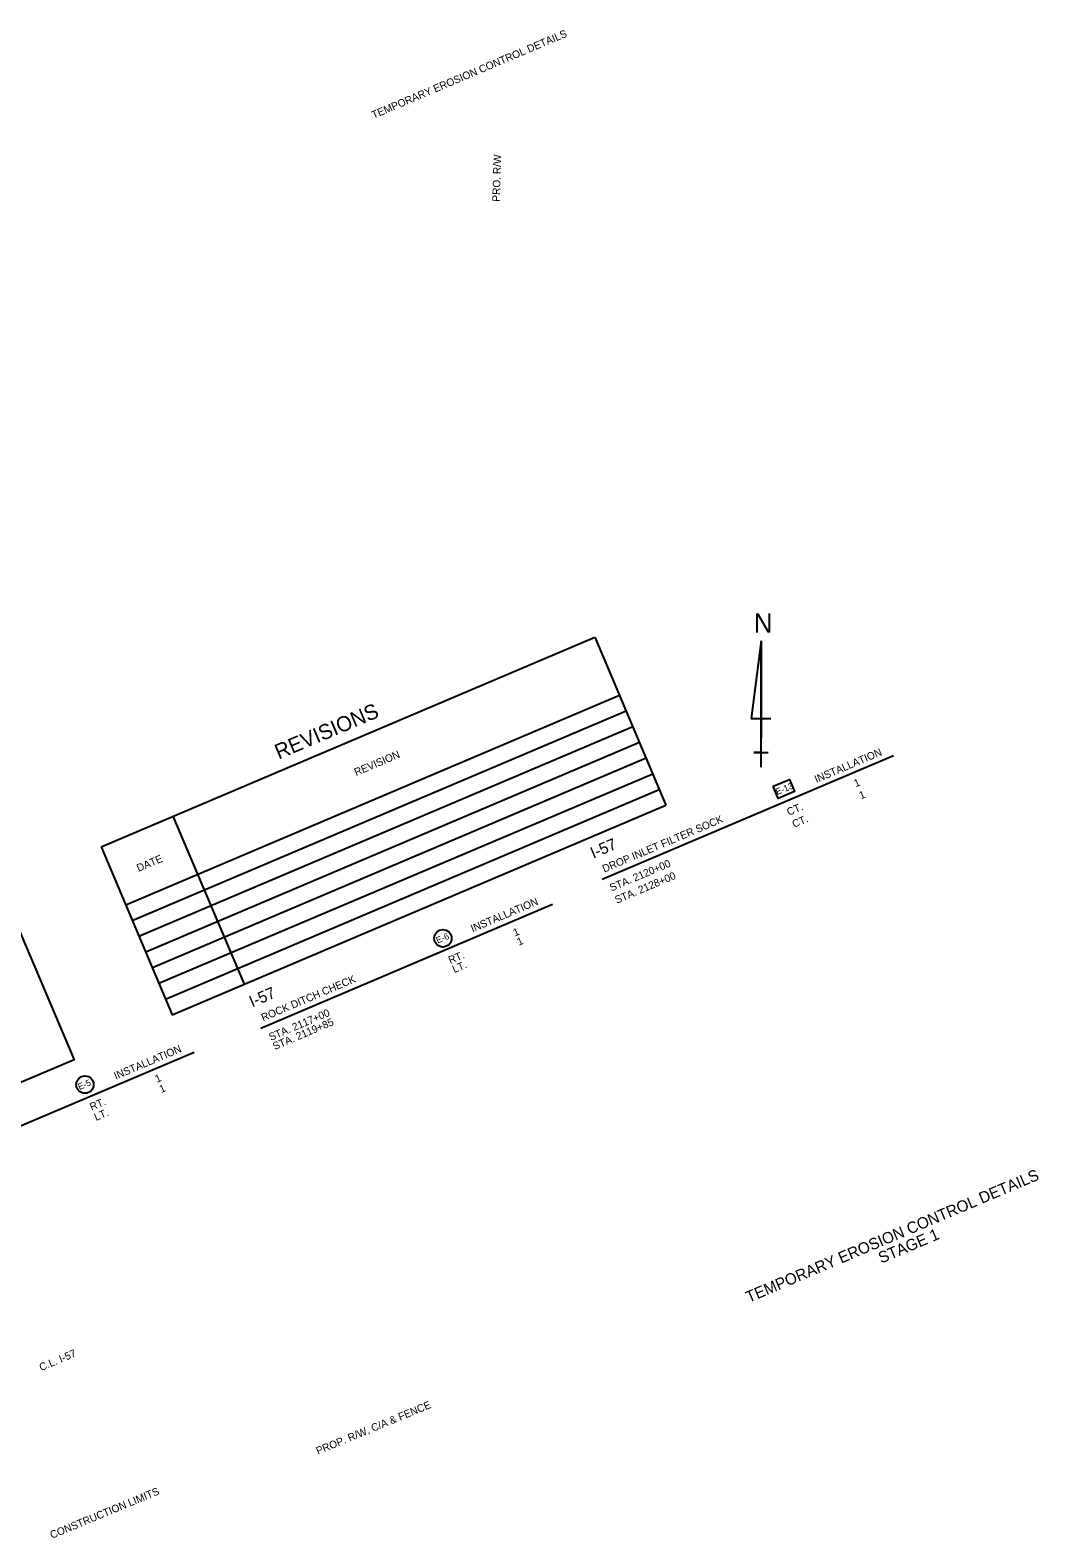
# Model space of a CAD drawing. Extents: x 1716086 to 1717910, y 765525 to 766719.
# Drawn here: x 1717110 to 1717910, y 765525 to 766719 of the extents above; entities that cross this region are included whole.
import ezdxf

# ---------------------------------------------------------------- set-up
doc = ezdxf.new("R2010")
doc.units = 0
for name, color, linetype in [('1', 7, 'Continuous'), ('44', 7, 'Continuous'), ('63', 7, 'Continuous'), ('Default', 7, 'Continuous'), ('G-ANNO-TEXT', 7, 'Continuous'), ('Level 44', 7, 'Continuous'), ('R_Draft', 7, 'Continuous')]:
    doc.layers.add(name, color=color, linetype=linetype)

msp = doc.modelspace()

# ---------------------------------------------------------------- linework, layer by layer
at = {"layer": '1'}
for points in [[(1717699.1, 766120.5), (1717712, 766126), (1717716.1, 766116.3), (1717703.2, 766110.9)], [(1716722.2, 765885.1), (1717087.4, 766040.1), (1717145.2, 765903.9), (1716780, 765749)]]:
    msp.add_lwpolyline(points, close=True, dxfattribs=at)
for centre in [(1717437.4, 766000.1), (1717153.8, 765884.2)]:
    msp.add_circle(centre, 6.88, dxfattribs=at)
at = {"layer": '44'}
for p, q in [((1717563.5, 766046.9), (1717794.5, 766144.9)), ((1717293.2, 765929), (1717524.3, 766027.1)), ((1717010.5, 765812.4), (1717240.2, 765909.9))]:
    msp.add_line(p, q, dxfattribs=at)
at = {"layer": '63'}
for p, q in [((1717689.5, 766235.7), (1717681.8, 766174.2)), ((1717689.5, 766135.7), (1717689.5, 766235.7)), ((1717689.5, 766235.7), (1717689.5, 766158.8)), ((1717681.8, 766174.2), (1717697.2, 766174.2)), ((1717689.5, 766135.7), (1717689.5, 766158.8)), ((1717689.5, 766147.3), (1717683.7, 766147.3)), ((1717683.7, 766147.3), (1717695.2, 766147.3)), ((1717689.5, 766135.7), (1717689.5, 766147.3))]:
    msp.add_line(p, q, dxfattribs=at)
at = {"layer": 'Default'}
for p, q in [((1717166.5, 766072.6), (1717557.7, 766238.7)), ((1717557.7, 766238.7), (1717614.2, 766105.7)), ((1717186.1, 766026.6), (1717577.3, 766192.7)), ((1717191.3, 766014.2), (1717582.6, 766180.2)), ((1717196.6, 766001.7), (1717587.8, 766167.8)), ((1717201.9, 765989.3), (1717593.1, 766155.4)), ((1717201.9, 765989.3), (1717593.1, 766155.4)), ((1717207.2, 765976.9), (1717598.4, 766143)), ((1717212.4, 765964.5), (1717603.7, 766130.5)), ((1717217.7, 765952), (1717608.9, 766118.1)), ((1717223, 765939.6), (1717614.2, 766105.7)), ((1717223.4, 766096.8), (1717279.9, 765963.8)), ((1717166.5, 766072.6), (1717223, 765939.6))]:
    msp.add_line(p, q, dxfattribs=at)

# ---------------------------------------------------------------- texts
at = {"layer": '1'}
for s, rotation, p in [('E-13', 22.6177, (1717702.4, 766113.6)), ('E-6 ', 23, (1717433.3, 765995.9)), ('E-5 ', 23, (1717149.5, 765879.9))]:
    msp.add_text(s, height=5, rotation=rotation, dxfattribs=at).set_placement(p)
at = {"layer": '44'}
for s, p in [('INSTALLATION', (1717733.4, 766123.1)), ('1', (1717764.6, 766119.7)), ('1', (1717768.7, 766110.1)), ('CT.', (1717711.5, 766097.1)), ('DROP INLET FILTER SOCK', (1717565.3, 766052.1)), ('CT.', (1717715.7, 766087.5)), ('STA. 2120+00', (1717571.1, 766037.1)), ('STA. 2128+00', (1717575.2, 766027.4)), ('INSTALLATION', (1717461, 766004.8)), ('1', (1717494.5, 766001.5)), ('1', (1717497.6, 765994.2)), ('RT.', (1717443.3, 765979.7)), ('LT.', (1717446.4, 765972.5)), ('ROCK DITCH CHECK', (1717295, 765934.3)), ('STA. 2117+00', (1717301, 765918.8)), ('STA. 2119+85', (1717304.1, 765911.5)), ('INSTALLATION', (1717178.3, 765888.1)), ('1', (1717210.8, 765885.6)), ('1', (1717214.2, 765877.5)), ('RT.', (1717159.1, 765863.5)), ('LT.', (1717162.6, 765855.4))]:
    msp.add_text(s, height=6, rotation=23, dxfattribs=at).set_placement(p)
at = {"layer": '63'}
msp.add_text('N', height=15.4, rotation=360, dxfattribs=at).set_placement((1717683.8, 766242.1))
at = {"layer": 'Default'}
for s, height, p in [('REVISIONS', 12, (1717307.3, 766141.6)), ('REVISION', 6, (1717368.7, 766128.6)), ('DATE', 6, (1717196.3, 766052.7))]:
    msp.add_text(s, height=height, rotation=23, dxfattribs=at).set_placement(p)
at = {"layer": 'G-ANNO-TEXT'}
for s, height, p in [('TEMPORARY EROSION CONTROL DETAILS', 6, (1717382.5, 766649.2)), ('TEMPORARY EROSION CONTROL DETAILS', 9, (1717679.8, 765711.3)), ('STAGE 1', 9, (1717784.8, 765742.4))]:
    msp.add_text(s, height=height, rotation=23, dxfattribs=at).set_placement(p)
at = {"layer": 'Level 44'}
for p in [(1717556.6, 766063.1), (1717286.3, 765945.3)]:
    msp.add_text('I-57', height=9.14, rotation=23, dxfattribs=at).set_placement(p)
at = {"layer": 'R_Draft'}
for s, rotation, p in [('PRO. R/W', 88.2527, (1717482.5, 766583.5)), ('C.L. I-57', 23, (1717119.1, 765657.2)), ('PROP. R/W, C/A & FENCE', 22.5, (1717338.4, 765591)), ('CONSTRUCTION LIMITS', 22.5, (1717127.6, 765524.4))]:
    msp.add_text(s, height=6, rotation=rotation, dxfattribs=at).set_placement(p)

doc.saveas('drawing.dxf')
